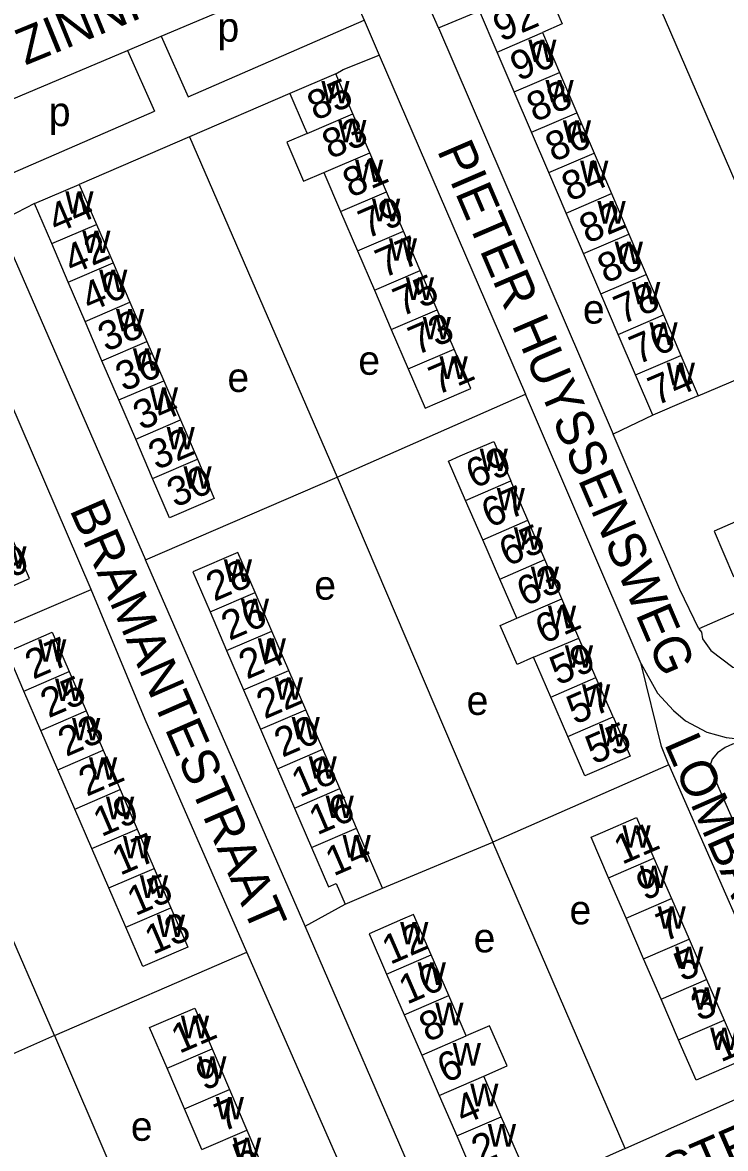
# Model space of a CAD drawing. Extents: x 158848 to 160613, y 385889 to 387762.
# Drawn here: x 159595.5 to 159691.8, y 386255.4 to 386409.7 of the extents above; entities that cross this region are included whole.
import ezdxf

# ---------------------------------------------------------------- set-up
doc = ezdxf.new("R2010")
doc.units = 0
for name, color, linetype in [('BLT_Basislijn', 7, 'Continuous'), ('BLT_Bebouwing', 7, 'Continuous'), ('BLT_Centroide', 7, 'Continuous'), ('BLT_Huisnummer', 7, 'Continuous'), ('BLT_Huisnummer_ tussenligend', 7, 'Continuous'), ('BLT_Onderverdeling_panden', 7, 'Continuous'), ('BLT_Spoorlijn', 7, 'Continuous'), ('BLT_Straatnaam', 7, 'Continuous')]:
    doc.layers.add(name, color=color, linetype=linetype)

msp = doc.modelspace()

# ---------------------------------------------------------------- linework, layer by layer
at = {"layer": 'BLT_Basislijn'}
for p, q in [((159679, 386420.49), (159703, 386364.88)), ((159652.47, 386408.91), (159650.57, 386413.29)), ((159652.47, 386408.91), (159658.09, 386411.24)), ((159618.16, 386399.49), (159642.29, 386409.95)), ((159642.29, 386409.95), (159644.32, 386405.2)), ((159609.86, 386405.82), (159614.47, 386407.77)), ((159614.47, 386407.77), (159618.16, 386399.49)), ((159652.47, 386408.91), (159676.41, 386353.28)), ((159609.86, 386405.82), (159613.57, 386397.5)), ((159644.32, 386405.2), (159664.38, 386358.76)), ((159632.11, 386399.95), (159618.35, 386393.99)), ((159589.89, 386387.24), (159613.57, 386397.5)), ((159618.35, 386393.99), (159603.25, 386387.48)), ((159618.35, 386393.99), (159638.58, 386347.38)), ((159597.11, 386384.84), (159592.13, 386382.31)), ((159592.13, 386382.31), (159612.31, 386336.07)), ((159604.87, 386332.01), (159584.47, 386379.32)), ((159688.02, 386358.52), (159703, 386364.88)), ((159638.58, 386347.38), (159664.38, 386358.76)), ((159680.22, 386321.82), (159664.38, 386358.76)), ((159681.81, 386355.87), (159676.41, 386353.28)), ((159612.31, 386336.07), (159638.58, 386347.38)), ((159638.58, 386347.38), (159659.93, 386297.36)), ((159634.21, 386285.86), (159612.31, 386336.07)), ((159578.22, 386320.6), (159604.87, 386332.01)), ((159683.04, 386310.49), (159680.22, 386321.82)), ((159599.85, 386270.89), (159578.22, 386320.6)), ((159684.02, 386307.99), (159683.04, 386310.49)), ((159684.02, 386307.99), (159659.93, 386297.36)), ((159684.02, 386307.99), (159702.31, 386266.24)), ((159644.8, 386291.09), (159659.93, 386297.36)), ((159678.05, 386255.44), (159659.93, 386297.36)), ((159634.21, 386285.86), (159639.69, 386288.89)), ((159599.85, 386270.89), (159626.22, 386282.32)), ((159599.85, 386270.89), (159573.77, 386259.36)), ((159599.85, 386270.89), (159618.05, 386228.56)), ((159678.05, 386255.44), (159702.31, 386266.24))]:
    msp.add_line(p, q, dxfattribs=at)
for points in [[(159614.47, 386407.77), (159637.5, 386417.49), (159638.83, 386417.79), (159642.29, 386409.95)], [(159589.89, 386387.24), (159587.65, 386392.22), (159587.21, 386395.58), (159587.6, 386396.03), (159591.86, 386398.22), (159609.86, 386405.82)], [(159638.38, 386402.64), (159639.39, 386403.21), (159644.32, 386405.2)], [(159727.27, 386375.16), (159737.64, 386351.03), (159738.25, 386349.53), (159738.18, 386348.46), (159688.12, 386326.6)], [(159688.12, 386326.6), (159685.53, 386331.97), (159676.41, 386353.28)], [(159626.22, 386282.32), (159612.29, 386314.17), (159604.87, 386332.01)], [(159688.12, 386326.6), (159688.52, 386326.13), (159688.64, 386325.25), (159689.76, 386323.65), (159692.78, 386321.35), (159696.43, 386321.18)], [(159680.22, 386321.82), (159682.46, 386317.8), (159684.64, 386315.42), (159686.3, 386314), (159689.23, 386312.45), (159691.89, 386311.72), (159694.38, 386311.44), (159696.97, 386311.7)], [(159678.05, 386255.44), (159655.24, 386245.22), (159652.47, 386245.09), (159651.36, 386246.27), (159650.39, 386248.42), (159634.21, 386285.86)], [(159618.05, 386228.56), (159642.1, 386239.2), (159643.48, 386241.21), (159643.15, 386243.72), (159626.22, 386282.32)]]:
    msp.add_lwpolyline(points, dxfattribs=at)
at = {"layer": 'BLT_Bebouwing'}
for p, q in [((159660.51, 386405.59), (159658.09, 386411.24)), ((159666.71, 386408.27), (159669.05, 386402.82)), ((159662.84, 386400.16), (159660.51, 386405.59)), ((159669.05, 386402.82), (159671.42, 386397.29)), ((159638.38, 386402.64), (159632.11, 386399.95)), ((159640.74, 386397.14), (159638.38, 386402.64)), ((159665.21, 386394.62), (159662.84, 386400.16)), ((159643.04, 386391.79), (159640.74, 386397.14)), ((159671.42, 386397.29), (159673.79, 386391.75)), ((159667.58, 386389.09), (159665.21, 386394.62)), ((159645.33, 386386.47), (159643.04, 386391.79)), ((159673.79, 386391.75), (159676.16, 386386.21)), ((159636.77, 386389.09), (159639.06, 386383.77)), ((159669.95, 386383.55), (159667.58, 386389.09)), ((159597.11, 386384.84), (159603.25, 386387.48)), ((159647.65, 386381.08), (159645.33, 386386.47)), ((159676.16, 386386.21), (159678.53, 386380.67)), ((159599.47, 386379.36), (159597.11, 386384.84)), ((159639.06, 386383.77), (159641.37, 386378.38)), ((159672.32, 386378.01), (159669.95, 386383.55)), ((159605.61, 386382), (159607.88, 386376.72)), ((159649.96, 386375.68), (159647.65, 386381.08)), ((159678.53, 386380.67), (159680.9, 386375.14)), ((159601.74, 386374.08), (159599.47, 386379.36)), ((159641.37, 386378.38), (159643.68, 386372.99)), ((159607.88, 386376.72), (159610.19, 386371.35)), ((159674.7, 386372.48), (159672.32, 386378.01)), ((159652.28, 386370.29), (159649.96, 386375.68)), ((159680.9, 386375.14), (159683.28, 386369.6)), ((159604.05, 386368.71), (159601.74, 386374.08)), ((159643.68, 386372.99), (159646, 386367.6)), ((159677.07, 386366.94), (159674.7, 386372.48)), ((159610.19, 386371.35), (159612.5, 386365.97)), ((159654.59, 386364.9), (159652.28, 386370.29)), ((159683.28, 386369.6), (159685.65, 386364.06)), ((159606.36, 386363.33), (159604.05, 386368.71)), ((159646, 386367.6), (159648.31, 386362.21)), ((159612.5, 386365.97), (159614.82, 386360.59)), ((159679.44, 386361.4), (159677.07, 386366.94)), ((159608.67, 386357.95), (159606.36, 386363.33)), ((159685.65, 386364.06), (159688.02, 386358.52)), ((159681.81, 386355.87), (159679.44, 386361.4)), ((159614.82, 386360.59), (159617.13, 386355.21)), ((159610.98, 386352.57), (159608.67, 386357.95)), ((159617.13, 386355.21), (159619.44, 386349.84)), ((159613.29, 386347.19), (159610.98, 386352.57)), ((159664.7, 386341.49), (159662.37, 386346.88)), ((159658.52, 386338.81), (159656.18, 386344.2)), ((159667.04, 386336.1), (159664.7, 386341.49)), ((159660.85, 386333.42), (159658.52, 386338.81)), ((159669.37, 386330.71), (159667.04, 386336.1)), ((159663.18, 386328.05), (159660.85, 386333.42)), ((159629.63, 386326.29), (159627.36, 386331.58)), ((159671.71, 386325.32), (159669.37, 386330.71)), ((159621.17, 386328.91), (159623.44, 386323.62)), ((159631.96, 386320.9), (159629.63, 386326.29)), ((159674.04, 386319.93), (159671.71, 386325.32)), ((159623.44, 386323.62), (159625.77, 386318.23)), ((159667.86, 386317.25), (159665.5, 386322.7)), ((159601.86, 386320.75), (159604.19, 386315.36)), ((159634.28, 386315.5), (159631.96, 386320.9)), ((159676.38, 386314.55), (159674.04, 386319.93)), ((159598, 386312.69), (159595.67, 386318.08)), ((159625.77, 386318.23), (159628.09, 386312.84)), ((159670.19, 386311.86), (159667.86, 386317.25)), ((159604.19, 386315.36), (159606.51, 386309.97)), ((159636.61, 386310.11), (159634.28, 386315.5)), ((159600.32, 386307.3), (159598, 386312.69)), ((159628.09, 386312.84), (159630.42, 386307.44)), ((159606.51, 386309.97), (159608.84, 386304.58)), ((159638.93, 386304.72), (159636.61, 386310.11)), ((159602.65, 386301.91), (159600.32, 386307.3)), ((159630.42, 386307.44), (159632.74, 386302.05)), ((159608.84, 386304.58), (159611.16, 386299.18)), ((159641.25, 386299.32), (159638.93, 386304.72)), ((159604.97, 386296.52), (159602.65, 386301.91)), ((159632.74, 386302.05), (159635.06, 386296.66)), ((159611.16, 386299.18), (159613.49, 386293.79)), ((159607.3, 386291.12), (159604.97, 386296.52)), ((159681.98, 386295.2), (159684.39, 386289.66)), ((159613.49, 386293.79), (159615.81, 386288.4)), ((159678.16, 386286.96), (159675.76, 386292.51)), ((159609.62, 386285.73), (159607.3, 386291.12)), ((159639.69, 386288.89), (159644.8, 386291.09)), ((159684.39, 386289.66), (159686.79, 386284.11)), ((159680.56, 386281.41), (159678.16, 386286.96)), ((159686.79, 386284.11), (159689.19, 386278.56)), ((159653.87, 386276.4), (159651.46, 386281.94)), ((159682.96, 386275.86), (159680.56, 386281.41)), ((159645.36, 386279.29), (159647.76, 386273.75)), ((159689.19, 386278.56), (159691.59, 386273.01)), ((159656.27, 386270.86), (159653.87, 386276.4)), ((159685.36, 386270.32), (159682.96, 386275.86)), ((159647.76, 386273.75), (159650.16, 386268.21)), ((159621.45, 386269.07), (159623.84, 386263.5)), ((159650.16, 386268.21), (159652.56, 386262.68)), ((159617.65, 386260.86), (159615.27, 386266.42)), ((159661.07, 386259.78), (159658.67, 386265.32)), ((159623.84, 386263.5), (159626.22, 386257.93)), ((159652.56, 386262.68), (159654.96, 386257.14)), ((159620.04, 386255.29), (159617.65, 386260.86)), ((159626.22, 386257.93), (159628.6, 386252.37))]:
    msp.add_line(p, q, dxfattribs=at)
for points in [[(159666.99, 386415.09), (159669.43, 386409.45), (159666.71, 386408.27)], [(159632.11, 386399.95), (159634.08, 386395.35), (159634.47, 386394.45)], [(159634.47, 386394.45), (159631.69, 386393.26), (159633.99, 386387.9), (159636.77, 386389.09)], [(159603.25, 386387.48), (159605.61, 386382)], [(159648.31, 386362.21), (159650.63, 386356.81), (159652.31, 386357.54), (159656.91, 386359.51), (159654.59, 386364.9)], [(159688.02, 386358.52), (159686.41, 386357.83), (159681.81, 386355.87)], [(159656.18, 386344.2), (159653.85, 386349.58), (159655.44, 386350.28), (159660.03, 386352.26), (159662.37, 386346.88)], [(159619.44, 386349.84), (159621.75, 386344.46), (159620.2, 386343.79), (159615.61, 386341.81), (159613.29, 386347.19)], [(159695.77, 386342.38), (159690.22, 386339.98), (159692.9, 386333.77), (159698.45, 386336.17)], [(159587.89, 386336.2), (159590.21, 386330.81), (159591.83, 386331.51), (159596.42, 386333.49), (159594.1, 386338.88)], [(159627.36, 386331.58), (159624.99, 386337.08), (159618.8, 386334.41), (159621.17, 386328.91)], [(159665.5, 386322.7), (159663.24, 386321.72), (159660.92, 386327.07), (159663.18, 386328.05)], [(159595.67, 386318.08), (159593.35, 386323.47), (159594.95, 386324.16), (159599.54, 386326.14), (159601.86, 386320.75)], [(159676.38, 386314.55), (159678.71, 386309.16), (159674.13, 386307.17), (159672.53, 386306.48), (159670.19, 386311.86)], [(159675.76, 386292.51), (159673.36, 386298.05), (159674.99, 386298.76), (159679.58, 386300.75), (159681.98, 386295.2)], [(159644.8, 386291.09), (159641.25, 386299.32)], [(159635.06, 386296.66), (159637.39, 386291.26), (159638.46, 386291.72), (159639.69, 386288.89)], [(159615.81, 386288.4), (159618.14, 386283.01), (159613.55, 386281.03), (159611.95, 386280.34), (159609.62, 386285.73)], [(159651.46, 386281.94), (159649.06, 386287.47), (159647.55, 386286.82), (159642.96, 386284.83), (159645.36, 386279.29)], [(159615.27, 386266.42), (159612.89, 386271.99), (159614.47, 386272.67), (159619.07, 386274.63), (159621.45, 386269.07)], [(159658.67, 386265.32), (159661.86, 386266.75), (159659.46, 386272.23), (159656.27, 386270.86)], [(159691.59, 386273.01), (159693.99, 386267.47), (159687.76, 386264.77), (159685.78, 386269.36), (159685.36, 386270.32)], [(159654.96, 386257.14), (159657.36, 386251.6), (159663.47, 386254.25), (159661.48, 386258.83), (159661.07, 386259.78)]]:
    msp.add_lwpolyline(points, dxfattribs=at)
at = {"layer": 'BLT_Onderverdeling_panden'}
for p, q in [((159660.51, 386405.59), (159666.71, 386408.27)), ((159662.84, 386400.16), (159669.05, 386402.82)), ((159634.47, 386394.45), (159640.74, 386397.14)), ((159665.21, 386394.62), (159671.42, 386397.29)), ((159636.77, 386389.09), (159643.04, 386391.79)), ((159667.58, 386389.09), (159673.79, 386391.75)), ((159639.06, 386383.77), (159645.33, 386386.47)), ((159669.95, 386383.55), (159676.16, 386386.21)), ((159599.47, 386379.36), (159605.61, 386382)), ((159641.37, 386378.38), (159647.65, 386381.08)), ((159672.32, 386378.01), (159678.53, 386380.67)), ((159601.74, 386374.08), (159607.88, 386376.72)), ((159643.68, 386372.99), (159649.96, 386375.68)), ((159674.7, 386372.48), (159680.9, 386375.14)), ((159604.05, 386368.71), (159610.19, 386371.35)), ((159646, 386367.6), (159652.28, 386370.29)), ((159677.07, 386366.94), (159683.28, 386369.6)), ((159606.36, 386363.33), (159612.5, 386365.97)), ((159648.31, 386362.21), (159654.59, 386364.9)), ((159679.44, 386361.4), (159685.65, 386364.06)), ((159608.67, 386357.95), (159614.82, 386360.59)), ((159610.98, 386352.57), (159617.13, 386355.21)), ((159613.29, 386347.19), (159619.44, 386349.84)), ((159656.18, 386344.2), (159662.37, 386346.88)), ((159658.52, 386338.81), (159664.7, 386341.49)), ((159660.85, 386333.42), (159667.04, 386336.1)), ((159621.17, 386328.91), (159627.36, 386331.58)), ((159663.18, 386328.05), (159669.37, 386330.71)), ((159623.44, 386323.62), (159629.63, 386326.29)), ((159665.5, 386322.7), (159671.71, 386325.32)), ((159595.67, 386318.08), (159601.86, 386320.75)), ((159625.77, 386318.23), (159631.96, 386320.9)), ((159667.86, 386317.25), (159674.04, 386319.93)), ((159598, 386312.69), (159604.19, 386315.36)), ((159628.09, 386312.84), (159634.28, 386315.5)), ((159670.19, 386311.86), (159676.38, 386314.55)), ((159600.32, 386307.3), (159606.51, 386309.97)), ((159630.42, 386307.44), (159636.61, 386310.11)), ((159602.65, 386301.91), (159608.84, 386304.58)), ((159632.74, 386302.05), (159638.93, 386304.72)), ((159604.97, 386296.52), (159611.16, 386299.18)), ((159635.06, 386296.66), (159641.25, 386299.32)), ((159675.76, 386292.51), (159681.98, 386295.2)), ((159607.3, 386291.12), (159613.49, 386293.79)), ((159678.16, 386286.96), (159684.39, 386289.66)), ((159609.62, 386285.73), (159615.81, 386288.4)), ((159680.56, 386281.41), (159686.79, 386284.11)), ((159645.36, 386279.29), (159651.46, 386281.94)), ((159682.96, 386275.86), (159689.19, 386278.56)), ((159647.76, 386273.75), (159653.87, 386276.4)), ((159685.36, 386270.32), (159691.59, 386273.01)), ((159650.16, 386268.21), (159656.27, 386270.86)), ((159615.27, 386266.42), (159621.45, 386269.07)), ((159652.56, 386262.68), (159658.67, 386265.32)), ((159617.65, 386260.86), (159623.84, 386263.5)), ((159654.96, 386257.14), (159661.07, 386259.78)), ((159620.04, 386255.29), (159626.22, 386257.93))]:
    msp.add_line(p, q, dxfattribs=at)
at = {"layer": 'BLT_Spoorlijn'}
msp.add_lwpolyline([(159693.78, 386311.09), (159692.74, 386310.8), (159691.72, 386310.37), (159690.67, 386309.62), (159689.97, 386308.75), (159689.61, 386307.69), (159700.89, 386281.94)], dxfattribs=at)

# ---------------------------------------------------------------- texts
at = {"layer": 'BLT_Centroide'}
for s, p in [('p', (159622.19, 386407.03)), ('w', (159664.76, 386404.25)), ('w', (159636.41, 386398.59)), ('w', (159667.12, 386398.72)), ('p', (159599.08, 386395.46)), ('w', (159638.72, 386393.22)), ('w', (159669.5, 386393.19)), ('w', (159641.03, 386387.81)), ('w', (159671.87, 386387.66)), ('w', (159601.34, 386383.47)), ('w', (159643.35, 386382.44)), ('w', (159674.24, 386382.12)), ('w', (159603.66, 386378.09)), ('w', (159645.66, 386377.03)), ('w', (159676.61, 386376.56)), ('w', (159605.97, 386372.72)), ('w', (159647.98, 386371.66)), ('w', (159678.98, 386371.03)), ('w', (159608.28, 386367.34)), ('e', (159672.25, 386368.41)), ('w', (159650.3, 386366.25)), ('w', (159681.36, 386365.5)), ('w', (159610.59, 386361.97)), ('e', (159641.48, 386361.4)), ('w', (159652.61, 386360.84)), ('w', (159683.73, 386359.97)), ('e', (159623.55, 386359.05)), ('w', (159612.91, 386356.59)), ('w', (159615.21, 386351.19)), ('w', (159658.11, 386348.22)), ('w', (159617.52, 386345.81)), ('w', (159660.44, 386342.84)), ('w', (159662.78, 386337.44)), ('w', (159592.16, 386334.84)), ('w', (159623.05, 386333.03)), ('w', (159665.11, 386332.06)), ('e', (159635.45, 386330.6)), ('w', (159625.38, 386327.66)), ('w', (159667.45, 386326.69)), ('w', (159597.61, 386322.09)), ('w', (159627.7, 386322.25)), ('w', (159669.78, 386321.28)), ('w', (159599.93, 386316.72)), ('w', (159630.02, 386316.88)), ('w', (159672.12, 386315.91)), ('e', (159656.32, 386314.81)), ('w', (159602.26, 386311.31)), ('w', (159632.34, 386311.47)), ('w', (159674.45, 386310.5)), ('w', (159604.58, 386305.94)), ('w', (159634.67, 386306.09)), ('w', (159606.91, 386300.53)), ('w', (159637, 386300.69)), ('w', (159677.66, 386296.62)), ('w', (159609.23, 386295.16)), ('w', (159639.32, 386295.28)), ('w', (159680.07, 386291.09)), ('w', (159611.55, 386289.75)), ('e', (159670.42, 386286.12)), ('w', (159613.88, 386284.38)), ('w', (159682.48, 386285.53)), ('w', (159647.21, 386283.38)), ('e', (159657.28, 386282.29)), ('w', (159684.87, 386280)), ('w', (159649.61, 386277.84)), ('w', (159687.27, 386274.44)), ('w', (159652.02, 386272.31)), ('w', (159617.17, 386270.53)), ('w', (159689.68, 386268.91)), ('w', (159654.41, 386266.78)), ('w', (159619.55, 386264.97)), ('w', (159656.81, 386261.22)), ('w', (159621.94, 386259.41)), ('e', (159610.32, 386256.48)), ('w', (159659.22, 386255.69)), ('w', (159624.31, 386253.84))]:
    msp.add_text(s, height=4, dxfattribs=at).set_placement(p)
at = {"layer": 'BLT_Huisnummer'}
for s, rotation, p in [('92', 23.1655, (159661.04, 386406.96)), ('85', 23.2261, (159635.59, 386396.15)), ('86', 23.1655, (159668.22, 386390.49)), ('44', 23.2633, (159600.08, 386380.71)), ('79', 23.2422, (159642.6, 386379.96)), ('82', 23.1655, (159672.86, 386379.31)), ('75', 23.2422, (159647.35, 386369.3)), ('78', 23.1655, (159677.6, 386368.24)), ('38', 23.2633, (159606.92, 386364.49)), ('71', 23.2422, (159652.26, 386358.56)), ('74', 23.1655, (159682.29, 386357.12)), ('34', 23.2633, (159611.73, 386353.74)), ('69', 23.4318, (159657.33, 386345.75)), ('30', 23.2633, (159616.38, 386343.16)), ('29', 23.3085, (159591.25, 386332.37)), ('28', 23.3144, (159621.73, 386330.31)), ('63', 23.4318, (159664.3, 386329.61)), ('27', 23.319, (159596.93, 386319.62)), ('59', 23.4318, (159668.83, 386318.81)), ('22', 23.3144, (159628.64, 386314.18)), ('55', 23.4318, (159673.73, 386307.97)), ('21', 23.319, (159604.27, 386303.59)), ('18', 23.3144, (159633.43, 386303.43)), ('11', 23.4104, (159677.61, 386294.26)), ('17', 23.319, (159608.84, 386292.76)), ('14', 23.3144, (159638.08, 386292.67)), ('13', 23.319, (159613.33, 386281.92)), ('12', 23.4371, (159645.84, 386280.55)), ('5', 23.406, (159685.84, 386278.23)), ('11', 23.1717, (159616.95, 386268.37)), ('1', 23.406, (159691.14, 386267.19)), ('6', 23.4371, (159653.41, 386264.32)), ('5', 23.1717, (159625.4, 386252.12)), ('2', 23.4371, (159658.1, 386253.15))]:
    msp.add_text(s, height=4, rotation=rotation, dxfattribs=at).set_placement(p)
at = {"layer": 'BLT_Huisnummer_ tussenligend'}
for s, rotation, p in [('90', 23.1655, (159663.4, 386401.57)), ('88', 23.1655, (159665.65, 386395.95)), ('83', 23.2422, (159637.63, 386390.89)), ('81', 23.2422, (159640.45, 386385.6)), ('84', 23.1655, (159670.44, 386385.08)), ('42', 23.2633, (159602.26, 386375.1)), ('77', 23.2422, (159644.93, 386374.6)), ('80', 23.1655, (159675.35, 386373.86)), ('40', 23.2633, (159604.66, 386369.95)), ('73', 23.2422, (159649.44, 386364.01)), ('76', 23.1655, (159679.73, 386362.74)), ('36', 23.2633, (159609.32, 386359.04)), ('32', 23.2633, (159613.83, 386348.3)), ('67', 23.4318, (159659.47, 386340.37)), ('65', 23.4318, (159661.89, 386335.08)), ('26', 23.3144, (159623.81, 386324.94)), ('61', 23.4318, (159666.84, 386324.46)), ('24', 23.3144, (159626.21, 386319.63)), ('25', 23.319, (159599.04, 386314.33)), ('57', 23.4318, (159671.15, 386313.43)), ('23', 23.319, (159601.45, 386309.03)), ('20', 23.3144, (159631.07, 386308.93)), ('16', 23.3144, (159635.83, 386298.29)), ('19', 23.319, (159606.27, 386298.06)), ('9', 23.406, (159680.69, 386289.31)), ('15', 23.319, (159610.92, 386287.22)), ('7', 23.406, (159683.42, 386283.68)), ('10', 23.4371, (159648.14, 386275.1)), ('3', 23.406, (159688.16, 386272.79)), ('8', 23.4371, (159650.93, 386269.94)), ('9', 23.1717, (159620.34, 386263.28)), ('4', 23.4371, (159655.84, 386258.61)), ('7', 23.1717, (159622.9, 386257.65))]:
    msp.add_text(s, height=4, rotation=rotation, dxfattribs=at).set_placement(p)
at = {"layer": 'BLT_Straatnaam'}
for s, height, rotation, p in [('VAN ZINNICQSTRAAT', 5, 22.2583, (159581.41, 386397.84)), ('PIETER HUYSSENSWEG', 5, 293.1754, (159652.21, 386392.15)), ('BRAMANTESTRAAT', 5, 293.521, (159601.87, 386342.91)), ('LOMBARDOPAD', 4.9999, 293.6667, (159683.33, 386310.87)), ('ANTHONY VAN OPBERGENSTRAAT', 5, 23.3855, (159603.62, 386214.54))]:
    msp.add_text(s, height=height, rotation=rotation, dxfattribs=at).set_placement(p)

doc.saveas('drawing.dxf')
